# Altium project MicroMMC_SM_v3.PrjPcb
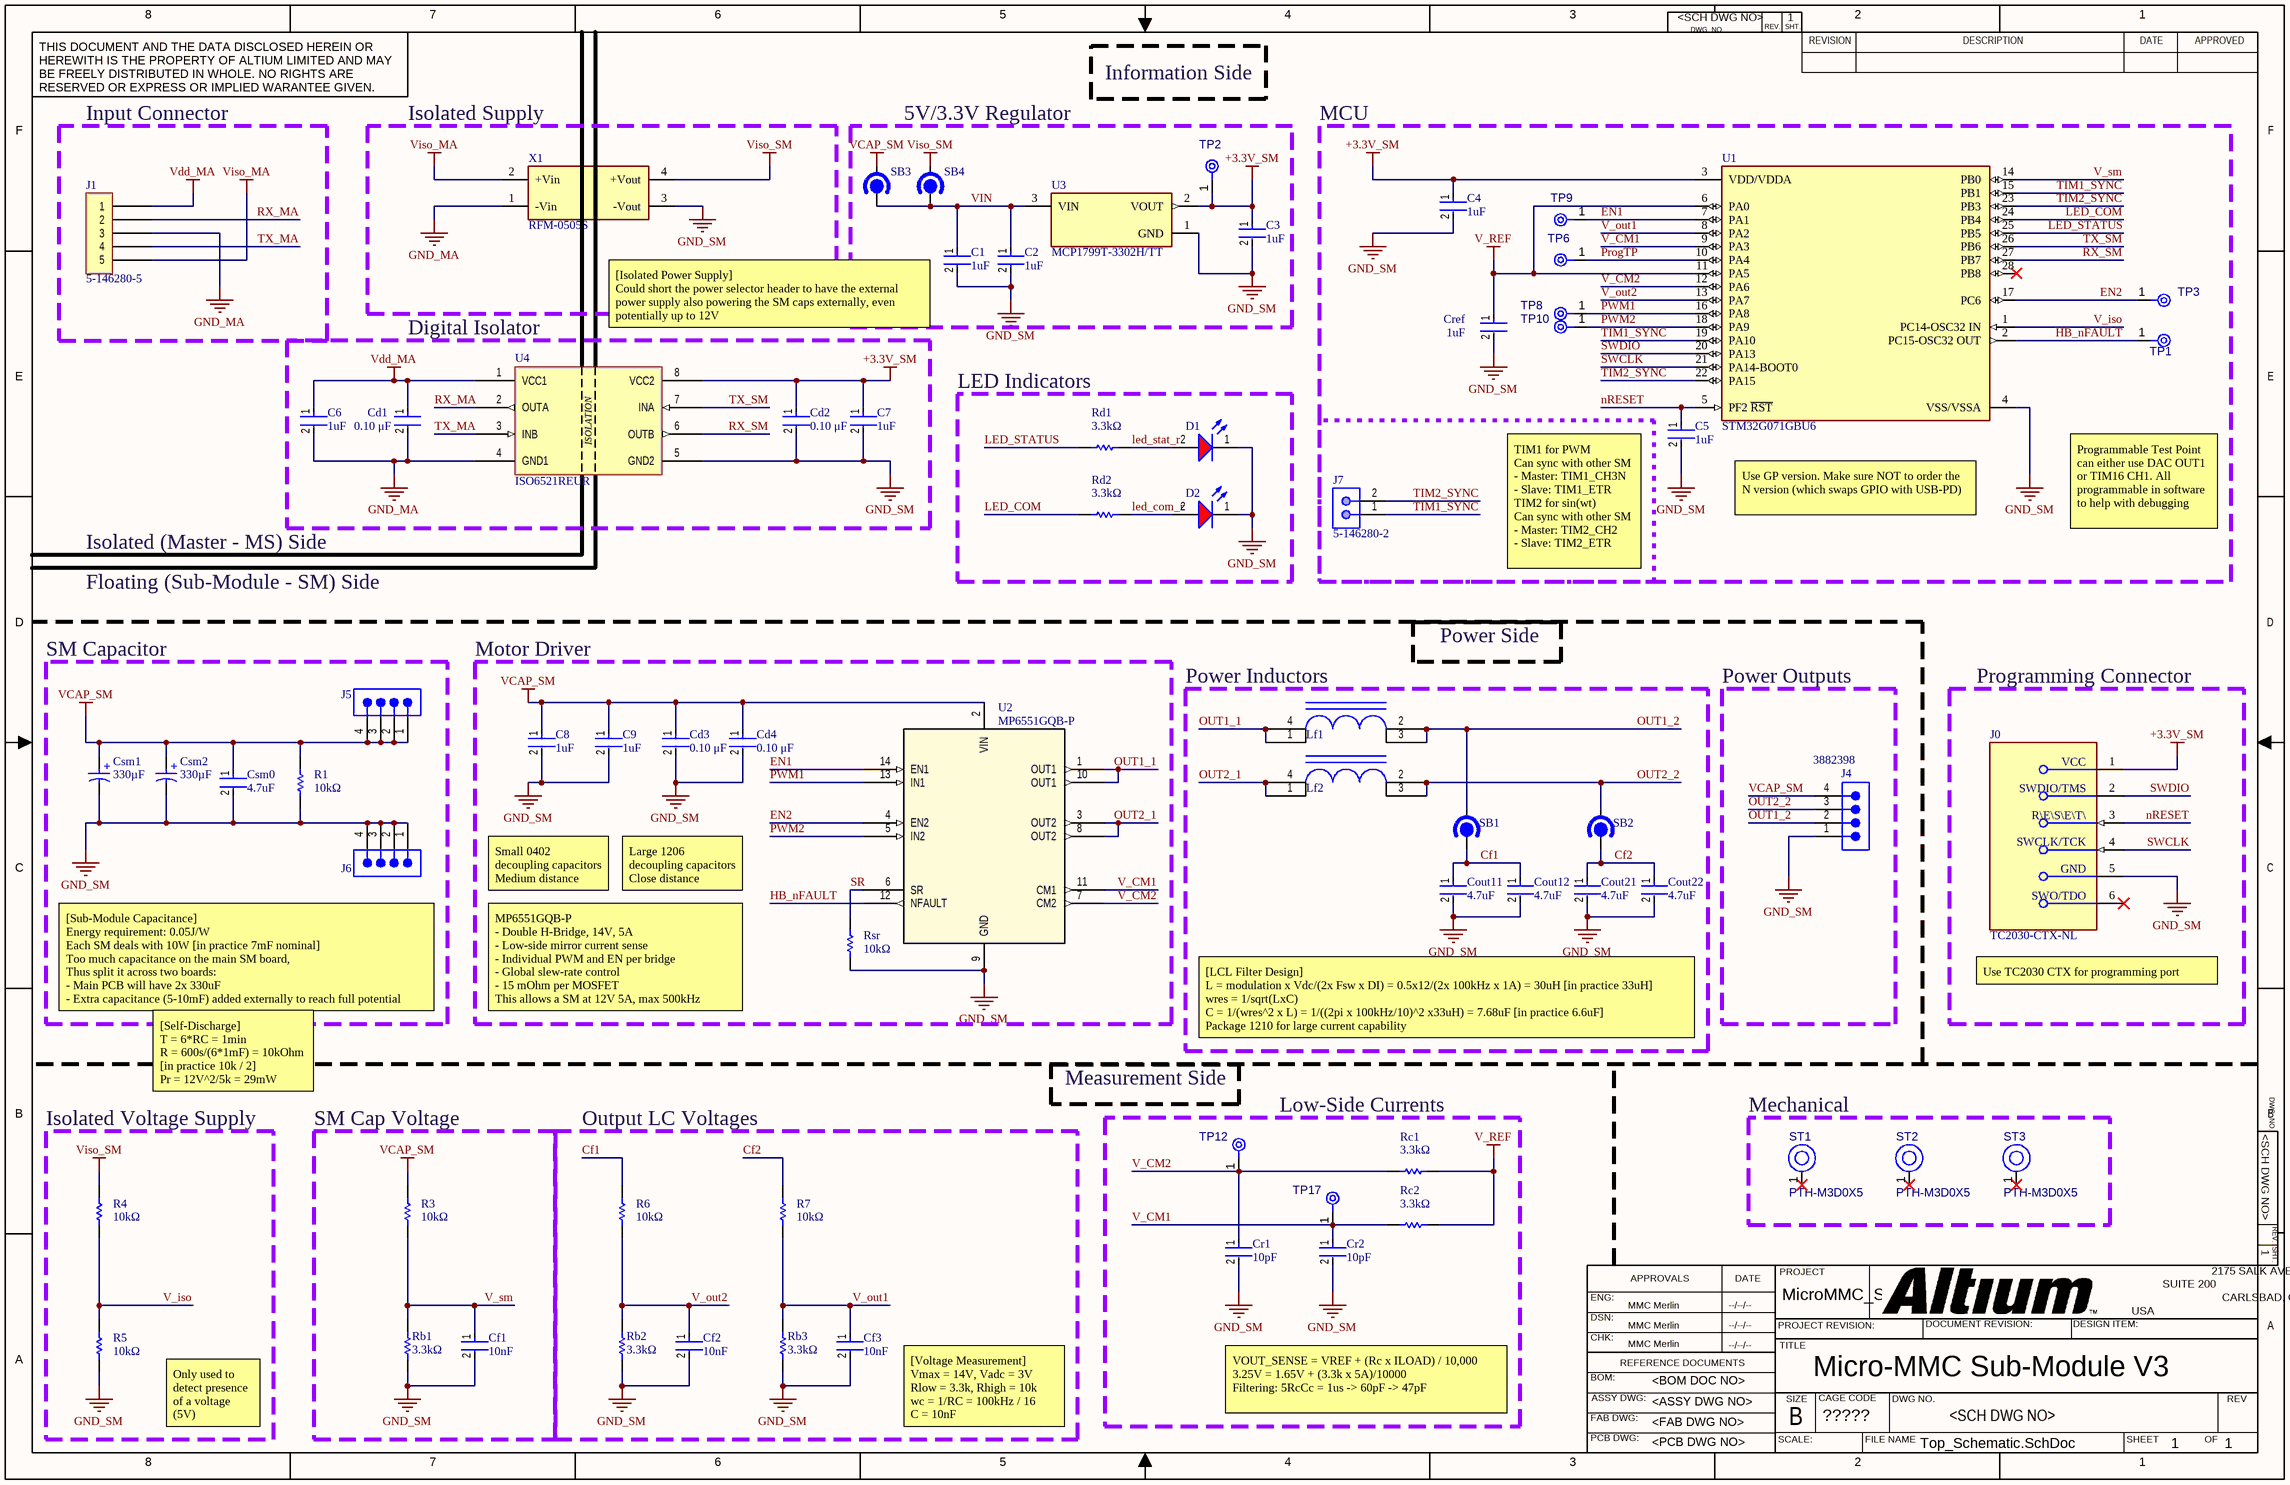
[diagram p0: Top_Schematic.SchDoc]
CAGE_CODE: ?????; CONTRACT_NUMBER: <CONTRACT NO>; DOC_NO_ASSY_DWG: <ASSY DWG NO>; DOC_NO_BOM: <BOM DOC NO>; DOC_NO_FAB_DWG: <FAB DWG NO>; DOC_NO_SCH_DWG: <SCH DWG NO>; PCB_2_DEC_TOL: +/-.01; PCB_3_DEC_TOL: +/-.010; PCB_ANG_TOL: +/-1/2; PCB_ASSEMBLY_NO: <PCB ASSY NO>; PCB_CHECKER: - -----; PCB_CHECKER_APP_DATE: --/--/----; PCB_DESIGNER: - -----; PCB_DESIGNER_APP_DATE: --/--/----; PCB_DWG_NO: <PCB DWG NO>; PCB_ENGINEER: - -----; PCB_ENGINEER_APP_DATE: --/--/----; PCB_PART_NUMBER: <PCB PN>; PCB_REV: A; SCH_REV: A
1 sheet, 71 parts. Net scope: global (net labels, ports and power ports of the same name join across sheets).
Board file: MicroMMC_SM_v3.PcbDoc

## Sheet Top_Schematic.SchDoc: Micro-MMC Sub-Module V3
size 431 x 279 mm; Date: 10/08/2023; ApprovedBy: MMC Merlin; CheckedBy: MMC Merlin; Author: MMC Merlin; CompanyName: University of Edinburgh; DrawnBy: MMC Merlin; Engineer: MMC Merlin; Organization: University of Edinburgh; Address1: School of Engineering; Address2: King's Buildings Campus; Address3: Edinburgh EH9 5FB; Address4: UK; DocumentNumber: 1; SheetNumber: 1; SheetTotal: 1; Project: MicroMMC_SM_V3; ENG_APP_DATE: --/--/--; DSN_APP_DATE: --/--/--; CHK_APP_DATE: --/--/--; SPICEModelCacheCJHNTGTK: <root> / <DocumentId>CJHNTGTK</DocumentId> / </root>

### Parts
C1  Capacitance: 1uF  [FP-GRM155-0_05-IPC_C]  (hidden comment: GRM155R61E105KA12D)
C2  Capacitance: 1uF  [FP-GRM155-0_05-IPC_C]  (hidden comment: GRM155R61E105KA12D)
C3  Capacitance: 1uF  [FP-GRM155-0_05-IPC_C]  (hidden comment: GRM155R61E105KA12D)
C4  Capacitance: 1uF  [FP-GRM155-0_05-IPC_C]  (hidden comment: GRM155R61E105KA12D)
C5  Capacitance: 1uF  [FP-GRM155-0_05-IPC_C]  (hidden comment: GRM155R61E105KA12D)
C6  Capacitance: 1uF  [FP-GRM155-0_05-IPC_C]  (hidden comment: GRM155R61E105KA12D)
C7  Capacitance: 1uF  [FP-GRM155-0_05-IPC_C]  (hidden comment: GRM155R61E105KA12D)
C8  Capacitance: 1uF  [FP-GRM155-0_05-IPC_C]  (hidden comment: GRM155R61E105KA12D)
C9  Capacitance: 1uF  [FP-GRM155-0_05-IPC_C]  (hidden comment: GRM155R61E105KA12D)
Cd1  Capacitance: 0.10 μF  [FP-C1206C-EB-MFG]  (hidden comment: C1206C104M5RACTU)
Cd2  Capacitance: 0.10 μF  [FP-C1206C-EB-MFG]  (hidden comment: C1206C104M5RACTU)
Cd3  Capacitance: 0.10 μF  [FP-C1206C-EB-MFG]  (hidden comment: C1206C104M5RACTU)
Cd4  Capacitance: 0.10 μF  [FP-C1206C-EB-MFG]  (hidden comment: C1206C104M5RACTU)
Cf1  Capacitance: 10nF  [FP-CL165-IPC_C]  (hidden comment: CL05B103KB5NNNC)
Cf2  Capacitance: 10nF  [FP-CL165-IPC_C]  (hidden comment: CL05B103KB5NNNC)
Cf3  Capacitance: 10nF  [FP-CL165-IPC_C]  (hidden comment: CL05B103KB5NNNC)
Cout11  Capacitance: 4.7uF  [FP-GRM21B-0_15-IPC_C]  (hidden comment: GRM21BR61H475ME51L)
Cout12  Capacitance: 4.7uF  [FP-GRM21B-0_15-IPC_C]  (hidden comment: GRM21BR61H475ME51L)
Cout21  Capacitance: 4.7uF  [FP-GRM21B-0_15-IPC_C]  (hidden comment: GRM21BR61H475ME51L)
Cout22  Capacitance: 4.7uF  [FP-GRM21B-0_15-IPC_C]  (hidden comment: GRM21BR61H475ME51L)
Cr1  Capacitance: 10pF  [FP-GJM155-0_05-MFG]  (hidden comment: GJM1555C1H100JB01D)
Cr2  Capacitance: 10pF  [FP-GJM155-0_05-MFG]  (hidden comment: GJM1555C1H100JB01D)
Cref  Capacitance: 1uF  [FP-GRM155-0_05-IPC_C]  (hidden comment: GRM155R61E105KA12D)
Csm0  Capacitance: 4.7uF  [FP-GRM21B-0_15-IPC_C]  (hidden comment: GRM21BR61H475ME51L)
Csm1  Capacitance: 330µF  [WCAP-ATG8_D8H11.5]  (hidden comment: 860010474012)
Csm2  Capacitance: 330µF  [WCAP-ATG8_D8H11.5]  (hidden comment: 860010474012)
D1  150060RS75000  [WL-SMCW_0603_150060xx75000]  (value not drawn)
D2  150060RS75000  [WL-SMCW_0603_150060xx75000]  (value not drawn)
J0  TC2030-CTX-NL  [FP-TC2030-CTX-NL-MFG]  (no BOM)
J1  5-146280-5  [5-146280-5]  (no BOM)
J4  Supplier Part Number 1: 3882398  [SMTC-TSW-104-08-X-S]  (hidden comment: TSW-104-08-L-S)  (no BOM)
J5  TSW-104-08-L-S  [SMTC-TSW-104-08-X-S]  (value not drawn)  (no BOM)
J6  TSW-104-08-L-S  [SMTC-TSW-104-08-X-S]  (value not drawn)  (no BOM)
J7  5-146280-2  [TECO-5-146280-2_V]  (no BOM)
Lf1  RCH1216BNP-100M  [TH Inductor]  (value not drawn)
Lf2  RCH1216BNP-100M  [TH Inductor]  (value not drawn)
R1  Resistance: 10kΩ  [RESC1005X40X25LL05T10]  (hidden comment: RC0402FR-0710KL)
R3  Resistance: 10kΩ  [RESC1005X40X25LL05T10]  (hidden comment: RC0402FR-0710KL)
R4  Resistance: 10kΩ  [RESC1005X40X25LL05T10]  (hidden comment: RC0402FR-0710KL)
R5  Resistance: 10kΩ  [RESC1005X40X25LL05T10]  (hidden comment: RC0402FR-0710KL)
R6  Resistance: 10kΩ  [RESC1005X40X25LL05T10]  (hidden comment: RC0402FR-0710KL)
R7  Resistance: 10kΩ  [RESC1005X40X25LL05T10]  (hidden comment: RC0402FR-0710KL)
Rb1  Resistance: 3.3kΩ  [RESC1005X40X25LL05T10]  (hidden comment: RC0402FR-073K3L)
Rb2  Resistance: 3.3kΩ  [RESC1005X40X25LL05T10]  (hidden comment: RC0402FR-073K3L)
Rb3  Resistance: 3.3kΩ  [RESC1005X40X25LL05T10]  (hidden comment: RC0402FR-073K3L)
Rc1  Resistance: 3.3kΩ  [RESC1005X40X25LL05T10]  (hidden comment: RC0402FR-073K3L)
Rc2  Resistance: 3.3kΩ  [RESC1005X40X25LL05T10]  (hidden comment: RC0402FR-073K3L)
Rd1  Resistance: 3.3kΩ  [RESC1005X40X25LL05T10]  (hidden comment: RC0402FR-073K3L)
Rd2  Resistance: 3.3kΩ  [RESC1005X40X25LL05T10]  (hidden comment: RC0402FR-073K3L)
Rsr  Resistance: 10kΩ  [RESC1005X40X25LL05T10]  (hidden comment: RC0402FR-0710KL)
SB1  Solder-Bridge-NO  [Solder-Bridge-NO-Footprint-1]  (value not drawn)  (no BOM)
SB2  Solder-Bridge-NO  [Solder-Bridge-NO-Footprint-1]  (value not drawn)  (no BOM)
SB3  Solder-Bridge-NO  [Solder-Bridge-NO-Footprint-1]  (value not drawn)  (no BOM)
SB4  Solder-Bridge-NO  [Solder-Bridge-NO-Footprint-1]  (value not drawn)  (no BOM)
ST1  PTH-M3D0X5  [PTH-M2D5X5]  (no BOM)
ST2  PTH-M3D0X5  [PTH-M2D5X5]  (no BOM)
ST3  PTH-M3D0X5  [PTH-M2D5X5]  (no BOM)
TP1  TPAD6R  [TP06R]  (value not drawn)  (no BOM)
TP2  TPAD6R  [TP06R]  (value not drawn)  (no BOM)
TP3  TPAD6R  [TP06R]  (value not drawn)  (no BOM)
TP6  TPAD6R  [TP06R]  (value not drawn)  (no BOM)
TP8  TPAD6R  [TP06R]  (value not drawn)  (no BOM)
TP9  TPAD6R  [TP06R]  (value not drawn)  (no BOM)
TP10  TPAD6R  [TP06R]  (value not drawn)  (no BOM)
TP12  TPAD6R  [TP06R]  (value not drawn)  (no BOM)
TP17  TPAD6R  [TP06R]  (value not drawn)  (no BOM)
U1  STM32G071GBU6  [FP-UFQFPN28-A0B0-MFG]
U2  MP6551GQB-P  [QFN-14_MP6551_MNP]
U3  MCP1799T-3302H/TT  [FP-C04-104-MFG]
U4  ISO6521REUR  [SON50P300X105-8N]
X1  RFM-0505S  [FP-RFM-0505S-MFG]

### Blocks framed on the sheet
Input Connector: J1
Isolated Supply: X1
5V/3.3V Regulator: C1-C3 SB3 SB4 TP2 U3
MCU: C4 C5 Cref J7 TP1 TP3 TP6 TP8-TP10 U1
Digital Isolator: C6 C7 Cd1 Cd2 U4
LED Indicators: D1 D2 Rd1 Rd2
SM Capacitor: Csm0-Csm2 J5 J6 R1
Motor Driver: C8 C9 Cd3 Cd4 Rsr U2
Power Inductors: Cout11 Cout12 Cout21 Cout22 Lf1 Lf2 SB1 SB2
Power Outputs: J4
Programming Connector: J0
Low-Side Currents: Cr1 Cr2 Rc1 Rc2 TP12 TP17
Mechanical: ST1-ST3
Isolated Voltage Supply: R4 R5
SM Cap Voltage: Cf1 R3 Rb1
Output LC Voltages: Cf2 Cf3 R6 R7 Rb2 Rb3

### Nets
+3.3V_SM: C3.1 C4.1 C7.1 Cd2.1 J0.1(VCC) TP2.1(TP) U1.3(VDD/VDDA) U3.2(VOUT) U4.8(VCC2)
GND_MA: C6.2 Cd1.2 J1.3 U4.4(GND1) X1.1(-Vin)
GND_SM: C1.2 C2.2 C3.2 C4.2 C5.2 C7.2 C8.2 C9.2 Cd2.2 Cd3.2 Cd4.2 Cf1.2 Cf2.2 Cf3.2 Cout11.2 Cout12.2 Cout21.2 Cout22.2 Cr1.2 Cr2.2 Cref.2 Csm0.2 Csm1.2(N) Csm2.2(N) D1.1(K) D2.1(K) J0.5(GND) J4.1 J6.1 J6.2 J6.3 J6.4 R1.1 R5.1 Rb1.1 Rb2.1 Rb3.1 Rsr.1 U1.4(VSS/VSSA) U2.9(GND) U3.1(GND) U4.5(GND2) X1.3(-Vout)
V_REF: Cref.1 Rc1.2 Rc2.2 U1.6(PA0) U1.11(PA5)
VCAP_SM: C8.1 C9.1 Cd3.1 Cd4.1 Csm0.1 Csm1.1(P) Csm2.1(P) J4.4 J5.1 J5.2 J5.3 J5.4 R1.2 R3.2 SB3.1 U2.2(VIN)
Vdd_MA: C6.1 Cd1.1 J1.1 U4.1(VCC1)
Viso_MA: J1.5 X1.2(+Vin)
Viso_SM: R4.2 SB4.1 X1.4(+Vout)
Cf1: Cout11.1 Cout12.1 R6.2 SB1.2
Cf2: Cout21.1 Cout22.1 R7.2 SB2.2
EN1: TP9.1(TP) U1.7(PA1) U2.14(EN1)
EN2: TP3.1(TP) U1.17(PC6) U2.4(EN2)
HB_nFAULT: TP1.1(TP) U1.2(PC15-OSC32_OUT) U2.12(NFAULT)
LED_COM: Rd2.1 U1.24(PB4)
led_com_r: D2.2(A) Rd2.2
led_stat_r: D1.2(A) Rd1.2
LED_STATUS: Rd1.1 U1.25(PB5)
nRESET: C5.1 J0.3(~{RESET}) U1.5(PF2_~{RST})
OUT1_1: Lf1.1 Lf1.4 U2.1(OUT1) U2.10(OUT1)
OUT1_2: J4.2 Lf1.2 Lf1.3 SB1.1
OUT2_1: Lf2.1 Lf2.4 U2.3(OUT2) U2.8(OUT2)
OUT2_2: J4.3 Lf2.2 Lf2.3 SB2.1
ProgTP: TP6.1(TP) U1.10(PA4)
PWM1: TP8.1(TP) U1.16(PA8) U2.13(IN1)
PWM2: TP10.1(TP) U1.18(PA9) U2.5(IN2)
RX_MA: J1.2 U4.2(OUTA)
RX_SM: U1.27(PB7) U4.6(OUTB)
SR: Rsr.2 U2.6(SR)
SWCLK: J0.4(SWCLK/TCK) U1.21(PA14-BOOT0)
SWDIO: J0.2(SWDIO/TMS) U1.20(PA13)
TIM1_SYNC: J7.1 U1.15(PB1) U1.19(PA10)
TIM2_SYNC: J7.2 U1.22(PA15) U1.23(PB3)
TX_MA: J1.4 U4.3(INB)
TX_SM: U1.26(PB6) U4.7(INA)
V_CM1: Cr2.1 Rc2.1 TP17.1(TP) U1.9(PA3) U2.11(CM1)
V_CM2: Cr1.1 Rc1.1 TP12.1(TP) U1.12(PA6) U2.7(CM2)
V_iso: R4.1 R5.2 U1.1(PC14-OSC32_IN)
V_out1: Cf3.1 R7.1 Rb3.2 U1.8(PA2)
V_out2: Cf2.1 R6.1 Rb2.2 U1.13(PA7)
V_sm: Cf1.1 R3.1 Rb1.2 U1.14(PB0)
VIN: C1.1 C2.1 SB3.2 SB4.2 U3.3(VIN)

Not connected (* = marked no-connect by the designer): J0 6(SWO/TDO)*; ST1 1(H1)*; ST2 1(H1)*; ST3 1(H1)*; U1 28(PB8)*

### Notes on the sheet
- Information Side
- (near C1) [Isolated Power Supply]
  Could short the power selector header to have the external power supply also powering the SM caps externally, even potentially up to 12V
- Isolated (Master - MS) Side
- (near C5) TIM1 for PWM
  Can sync with other SM
  - Master: TIM1_CH3N
  - Slave: TIM1_ETR
  TIM2 for sin(wt)
  Can sync with other SM
  - Master: TIM2_CH2
  - Slave: TIM2_ETR
- Use GP version. Make sure NOT to order the N version (which swaps GPIO with USB-PD)
- Programmable Test Point can either use DAC OUT1 or TIM16 CH1. All programmable in software to help with debugging
- Floating (Sub-Module - SM) Side
- Power Side
- Small 0402 decoupling capacitors
  Medium distance
- Large 1206 decoupling capacitors
  Close distance
- [Sub-Module Capacitance]
  Energy requirement: 0.05J/W
  Each SM deals with 10W [in practice 7mF nominal]
  Too much capacitance on the main SM board,
  Thus split it across two boards:
  - Main PCB will have 2x 330uF
  - Extra capacitance (5-10mF) added externally to reach full potential
- MP6551GQB-P
  - Double H-Bridge, 14V, 5A
  - Low-side mirror current sense
  - Individual PWM and EN per bridge
  - Global slew-rate control
  - 15 mOhm per MOSFET
  This allows a SM at 12V 5A, max 500kHz
- [LCL Filter Design]
  L = modulation x Vdc/(2x Fsw x DI) = 0.5x12/(2x 100kHz x 1A) = 30uH [in practice 33uH]
  wres = 1/sqrt(LxC)
  C = 1/(wres^2 x L) = 1/((2pi x 100kHz/10)^2 x33uH) = 7.68uF [in practice 6.6uF]
  Package 1210 for large current capability
- Use TC2030 CTX for programming port
  NOT MCP!!!
- [Self-Discharge]
  T = 6*RC = 1min
  R = 600s/(6*1mF) = 10kOhm [in practice 10k / 2]
  Pr = 12V^2/5k = 29mW
- Measurement Side
- Only used to detect presence of a voltage (5V)
- [Voltage Measurement]
  Vmax = 14V, Vadc = 3V
  Rlow = 3.3k, Rhigh = 10k
  wc = 1/RC = 100kHz / 16
  C = 10nF
- VOUT_SENSE = VREF + (Rc x ILOAD) / 10,000
  3.25V = 1.65V + (3.3k x 5A)/10000
  Filtering: 5RcCc = 1us -> 60pF -> 47pF

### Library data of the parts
C1-C9 Cref = CMP-2008-04581-2: Chip Multilayer Ceramic Capacitors for General Purpose, 0402, 1.0uF, X5R, 15%, 10%, 25V
Cd1-Cd4 = CMP-03020-028488-1: CAP CER 0.1UF 50V X7R 1206; Manufacturer: KEMET; Automotive Grade: Grade 0; Value: 0.10 μF; Tolerance: 0.2; Temperature Coefficient: 15%
Cf1-Cf3 = CMP-13271-000387-1: Cap Ceramic 10nF 50V X7R ±10% SMD 0402 +125°C Paper T/R
Cout11 Cout12 Cout21 Cout22 Csm0 = CMP-06035-037765-1: Chip Multilayer Ceramic Capacitors for General Purpose, 0805, 4.7uF, X5R, 15%, 20%, 50V
Cr1 Cr2 = CMP-2008-03797-2: Multi-Layer Ceramic Capacitor 10pF C0G  ±5% 0402 Paper T/R; Voltage Rating (DC): 50V
Csm1 Csm2 = CMP-03913-54007214-1: 860010474012 WCAP-ATG8 Aluminum Electrolytic Capacitors; Manufacturer: Panasonic; Manufacturer Part Number: ECA-1CHG471; Pitch: 3.5mm; Life (Hours): 2000hours; Voltage Rating (DC): 25V; Polarity: Polar; Tolerance: 20%; Leakage Current: 82.5µA; Ripple Current: 451mA; Dielectric Material: Aluminium; Value: 470uF; Rated DC Voltage (URdc): 16V; Tan Delta: 0.2
D1 D2 = CMP-1426-00001-4: LED Low-Power Uni-Color Red 630nm 2V 2-Pin Chip 0603(1608Metric) T/R; Max Junction Temperature (Tj): 95°C; Dominant Wavelength: 625nm; Lens Style: Clear, Rectangular; Viewing Angle: 140°; Forward Current: 100mA; Max Reverse Voltage (DC): 5V; Luminous Intensity: 250mcd; Test Current: 20mA; Power Dissipation: 72mW
J0 = CMP-205963-000001-1: 6-Pin “No legs” TC2030 Plug-of-Nails™ Cable for use with ARM Cortex processors
J1 = CMP-002-00297-1: Board Connector, 5 Contact(s), 1 Row(s), Male, Straight, Solder Terminal
J4-J6 = CMP-1024-00358-1: 0.025" SQ Post Header, Through-hole, Vertical, -55 to 125 degC, 2.54 mm Pitch, 4-Pin, Male, RoHS; Manufacturer: Samtec; Manufacturer Part Number: G800W304018EU; Pitch: 2.54 mm; Connector Type: BOARD CONNECTOR; Option: General Purpose; Filter Feature: No; Number of Rows Loaded: 1; Number of Contacts: 4
J7 = CMP-2000-07492-1: Male Header, Pitch 2.54 mm, 1 x 2 Position, Height 8.21 mm, Tail Length 3.05 mm, -65 to 105 degC, RoHS, Bulk; Manufacturer: TE Connectivity; Mating Connector Lock: No(Without); Number of Positions: 2; Pitch: 2.54mm; PCB Mounting Orientation: Vertical; Keyed: No; Case\/Package: 100; Mating Post Length: 0.23inch; High Temperature Housing: Yes; Max Current Rating: 5A; PCB Thickness: 0.063inch; PCB Mount Retention: Without; Approvals: CSA; Current Rating: 3A
Lf1 Lf2 = CMP-006-00026-4: Ind Power Unshielded Wirewound 10uH 20% 1KHz Ferrite 5A Pin Box
R1 R3-R7 Rsr = CMP-2002-07353-1: Manufacturer: Yageo / Phycomp
Rb1-Rb3 Rc1 Rc2 Rd1 Rd2 = CMP-2002-07652-1: 3.3k; Manufacturer: Yageo / Phycomp
SB1-SB4 = CMP-00030-00003-3: Normally Open Solder Bridge 10mil gap
ST1-ST3 = CMP-00028-00004-1: M3.0 PTH (3.0mm), 5mm pad
TP1-TP3 TP6 TP8-TP10 TP12 TP17 = CMP-00028-00002-1: 0.6mm round
U1 = CMP-12105-000098-1: IC MCU 32BIT 128KB FLSH 28UFQFPN; Frequency: 64MHz; Interface: I2C; Core Architecture: ARM; Memory Type: FLASH; Peripherals: Brown-out Detect/Reset; Oscillator Type: Internal; Number of I/Os: 26
U2 = CMP-024-00000-3: Brushed DC Motor Driver Dual Half-Bridge PWM 2.5V to 14V 5A 14-Pin QFN
U3 = CMP-06324-000112-1: IC REG LINEAR 3.3V 80MA SOT23-3
U4 = CMP-015-00010-3: Functional isolation dual-channel 1/1 digital isolator 8-VSON -40 to 125
X1 = CMP-29842-000017-1: DC DC CONVERTER 5V 1W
